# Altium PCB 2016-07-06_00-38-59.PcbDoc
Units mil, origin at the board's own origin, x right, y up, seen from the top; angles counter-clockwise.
Board outline 1500 x 1800 mil, 4 copper layers (Top Layer, MidLayer1, MidLayer2, Bottom Layer); 14 components, 7 nets, 31 pads, 11 vias.
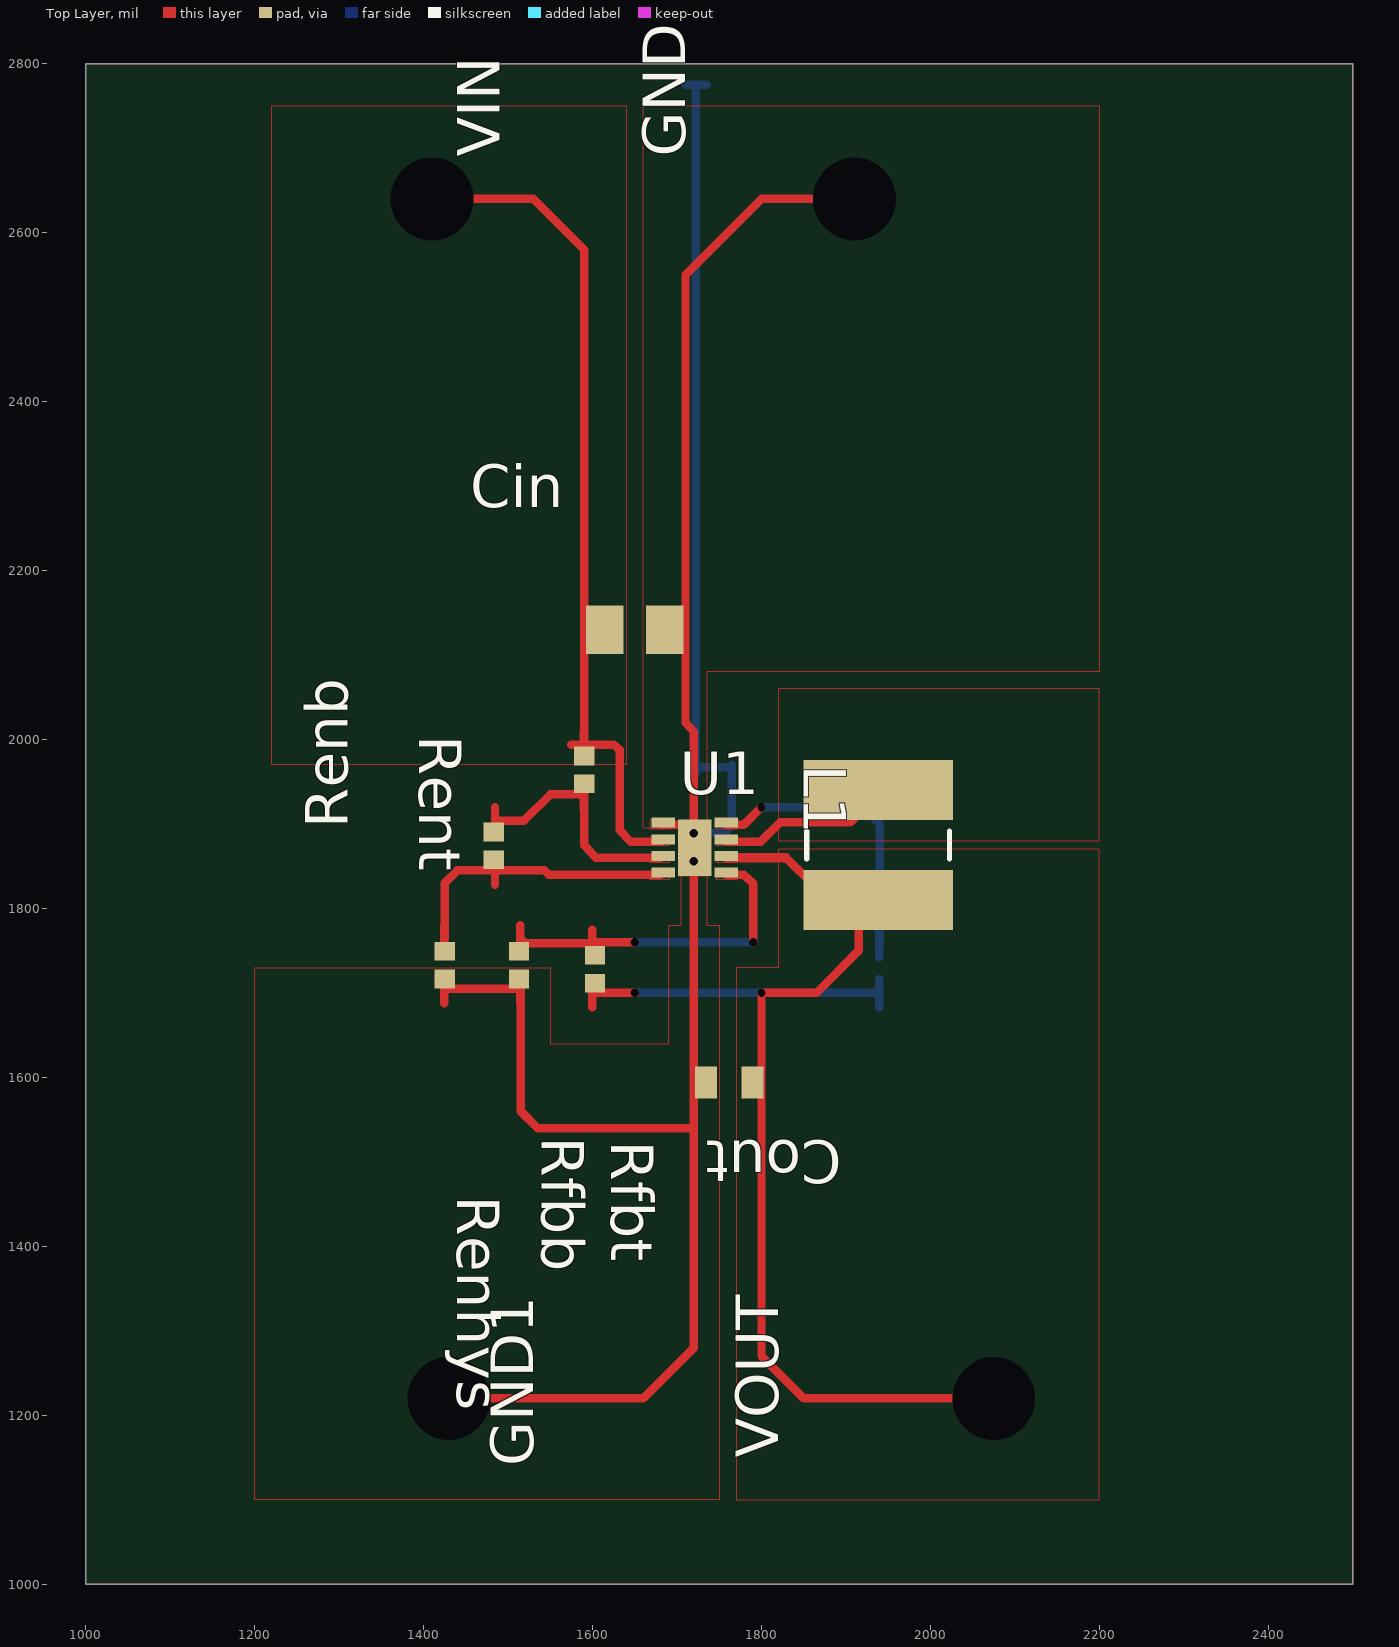
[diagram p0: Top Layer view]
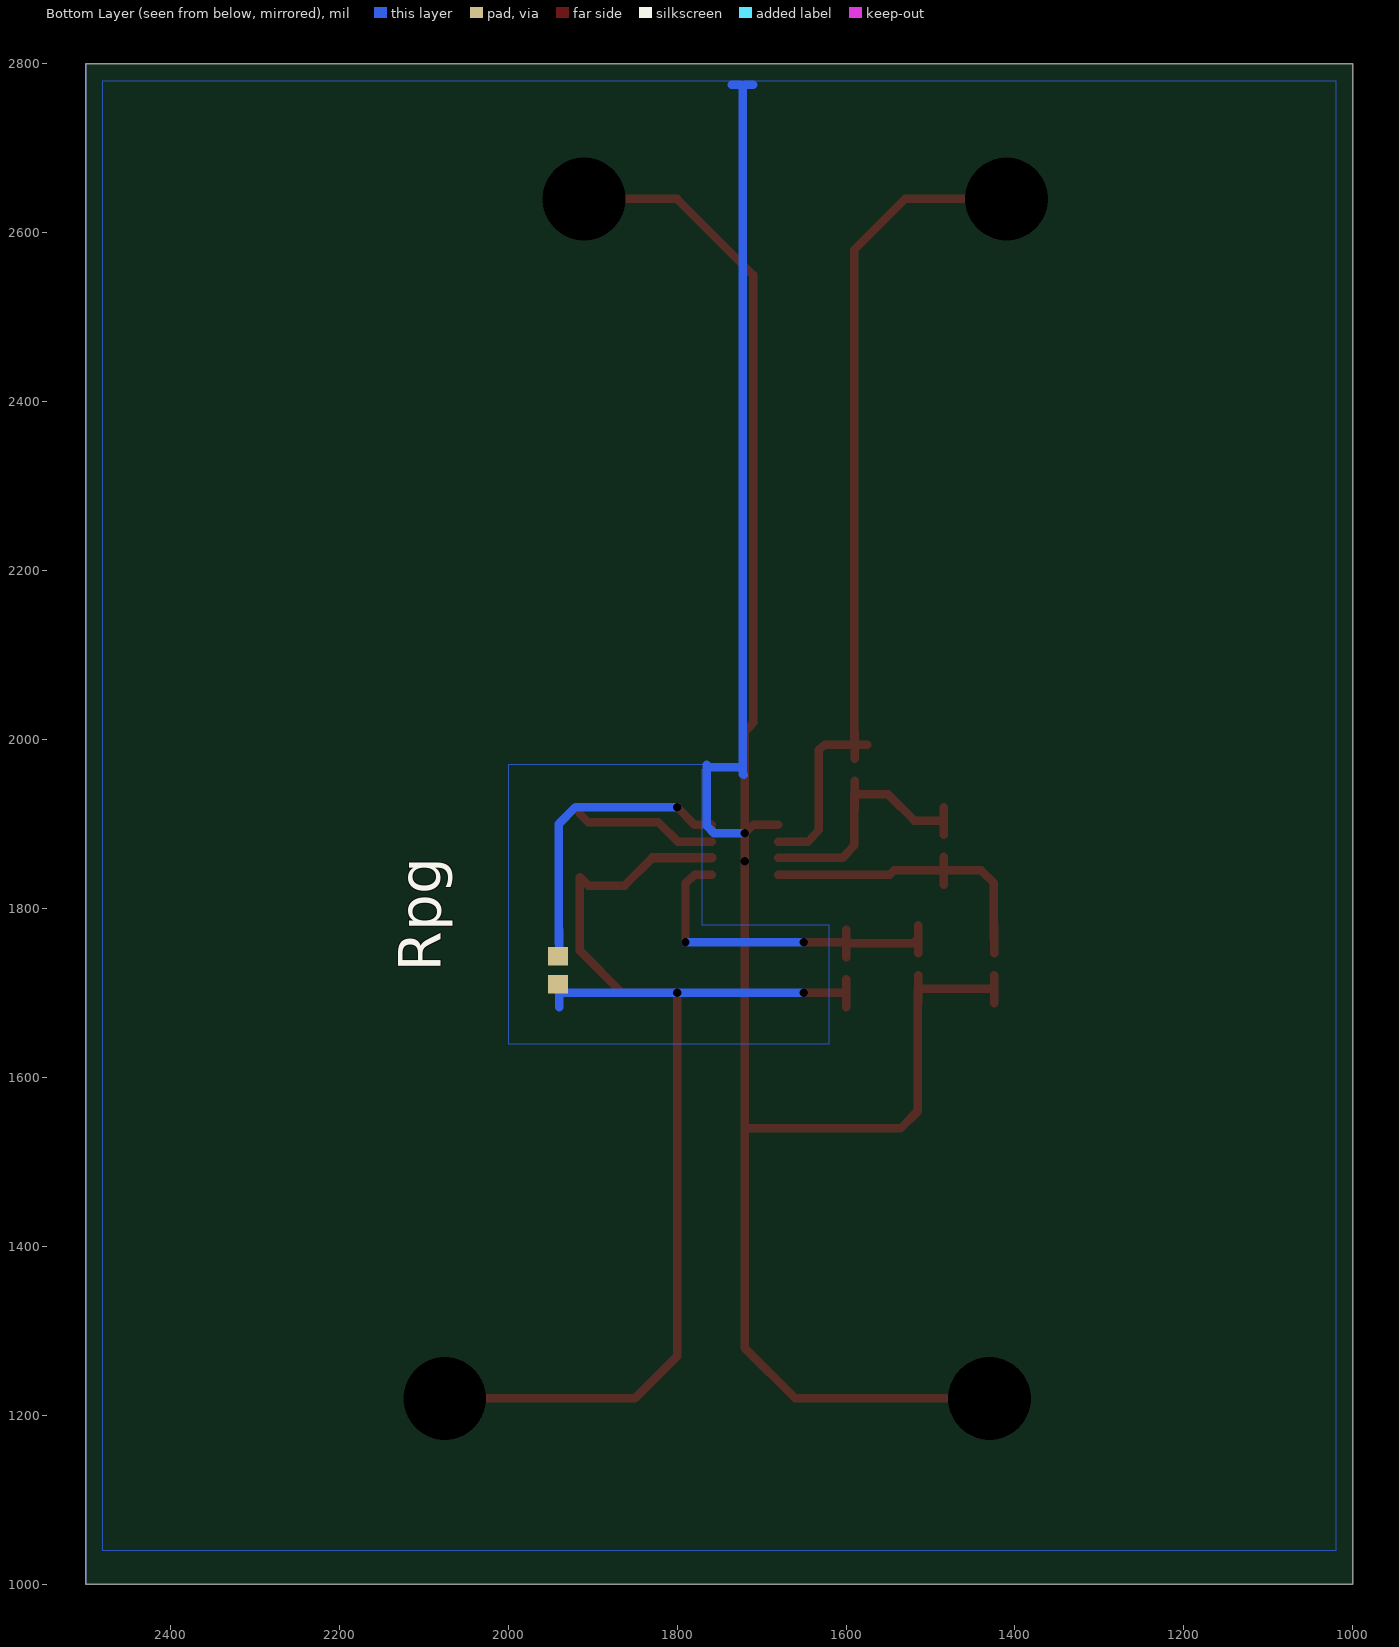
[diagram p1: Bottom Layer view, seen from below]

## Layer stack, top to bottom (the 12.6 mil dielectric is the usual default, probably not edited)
Top Layer: signal copper 1.4
Dielectric: core 12.6, FR-4, Dk 4.8
MidLayer1: signal copper 1.4
Dielectric: prepreg 12.6, FR-4, Dk 4.8
MidLayer2: signal copper 1.4
Dielectric: core 12.6, FR-4, Dk 4.8
Bottom Layer: signal copper 1.4

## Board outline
1000,1000 2500,1000 2500,2800 1000,2800

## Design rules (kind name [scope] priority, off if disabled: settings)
PlaneConnect [All] p0: scope1count=1 scope1_0_kind=Board scope1_0_value=Board scope2count=1 scope2_0_kind=Board scope2_0_value=Board commentlength=0 planeconnectstyle=Direct reliefexpansion=20 reliefentries=4 reliefconductorwidth=10 reliefairgap=10
PlaneConnect [All] p1: planeconnectstyle=Direct reliefexpansion=20 reliefentries=4 reliefconductorwidth=10 reliefairgap=10
PolygonConnect [All] p0: scope1count=1 scope1_0_kind=Board scope1_0_value=Board scope2count=1 scope2_0_kind=Board scope2_0_value=Board commentlength=0 connectstyle=Direct reliefconductorwidth=10 reliefentries=4 polygonreliefangle="90 Angle"
PolygonConnect [All] p1: connectstyle=Direct reliefconductorwidth=10 reliefentries=4 polygonreliefangle="90 Angle"

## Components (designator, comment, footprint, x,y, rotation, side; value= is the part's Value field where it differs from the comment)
Cin "" 0805 1650,2130 r0 top
Cout "" 0603 1762,1594 r180 top
GND "" TP-1502 1909,2638 r90 top
GND1 "" TP-1502 1429,1219 r90 top
L1 "" SDR0403 1938,1875 r270 top
Renb "" 0402#1 1483,1874 r90 top
Renhys "" 0402#1 1425,1733 r270 top
Rent "" 0402#1 1590,1964 r270 top
Rfbb "" 0402#1 1513,1733 r270 top
Rfbt "" 0402#1 1603,1728 r270 top
Rpg "" 0402#2 1941,1727 r270 bottom
U1 "" S-PWSON-N8 1721,1872 r0 top
VIN "" TP-1502 1409,2638 r90 top
VOUT "" TP-1502 2074,1219 r90 top

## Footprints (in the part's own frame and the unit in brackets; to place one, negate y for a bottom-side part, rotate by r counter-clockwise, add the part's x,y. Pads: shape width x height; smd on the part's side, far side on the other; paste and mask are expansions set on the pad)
0402#1 [mil]
  rect 22x24 smd: 1(-16.5,0) 2(16.5,0)
0402#2 [mil]
  rect 22x24 smd: 1(16.5,0) 2(-16.5,0)
0603 [mil]
  rect 26x38 smd: 1(-27.5,0) 2(27.5,0)
0805 [mil]
  rect 44x57 smd: 1(-35.5,0) 2(35.5,0)
S-PWSON-N8 [mm]
  rect 0.705x0.3 smd: 1(-0.952,0.75) 2(-0.952,0.25) 3(-0.952,-0.25) 4(-0.952,-0.75) 5(0.952,-0.75) 6(0.952,-0.25) 7(0.952,0.25) 8(0.952,0.75)
  rect 1x1.7 smd: 9(0,0)
SDR0403 [mil]
  rect 71x177 smd: 1(-65,0) 2(65,0)
  silkscreen extent -16,-84 16,84
TP-1502 [mil]
  round 65 / inner round 0 / far side round 65 hole 32: 1(0,0)

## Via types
v1: diameter 0, hole 10, Top Layer to Bottom Layer, 7 vias
v2: diameter 0, hole 98, Top Layer to Bottom Layer, 4 vias

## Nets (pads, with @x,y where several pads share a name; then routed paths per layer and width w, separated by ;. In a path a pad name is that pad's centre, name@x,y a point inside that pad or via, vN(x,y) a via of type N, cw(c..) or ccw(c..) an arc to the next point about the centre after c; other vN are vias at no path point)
0: Cin.2 Cout.2 GND1.1 GND.1 Renhys.2 Rfbb.2 U1.1 U1.9 | length 3391.8
  Top Layer w10: 1424.5,1688 Renhys.2@1424.5,1721 ; 1425,1705 1515,1705 1515,1560 1535,1540 1720,1540 ; v2(1430,1220) 1660,1220 1720,1280 1720,1540 ; 1514.5,1688 Rfbb.2@1514.5,1721 ; U1.1@1680,1899 1710,1899 v1(1720,1889) ; v2(1910,2640) 1800,2640 1710,2550 1710,2170 1710,2020 1720,2009 v1(1720,1889) ; 1720,1540 1720,1869 v1(1720,1889)
  Bottom Layer w10: 1710,2775 1722,2775 ; v1(1720,1889) 1756,1889 1765,1898 1765,1970 1762,1967 1722,1967 ; 1721,1958 1722,1959 1722,1967 ; 1735,2775 1722,2775 ; 1722,1967 1722,2775
  other v1: 1720,1856
1: Renb.1 Renhys.1 U1.4 | length 395.3
  Top Layer w10: Renhys.1@1424.5,1747 1424.5,1780 ; 1425,1764 1425,1830 1440,1845 1485,1845 1543,1845 1548,1840 U1.4@1680,1840 ; 1484.5,1828 Renb.1@1484.5,1861
2: Renb.2 Rent.2 U1.3 | length 340.4
  Top Layer w10: Renb.2@1484.5,1887 1484.5,1920 ; 1485,1904 1519,1904 1550,1935 1590,1935 1590,1875 1604,1860 U1.3@1680,1860 ; 1589.5,1918 Rent.2@1589.5,1951
5: Rfbb.1 Rfbt.1 U1.5 | length 448.9
  Top Layer w10: Rfbb.1@1514.5,1747 1514.5,1780 ; 1515,1764 1520,1759 1600,1759 1600,1760 v1(1650,1760) ; Rfbt.1@1599.5,1742 1599.5,1775 ; U1.5@1759,1840 1779,1840 1790,1830 v1(1790,1760)
  Bottom Layer w10: v1(1650,1760) v1(1790,1760)
6: Cout.1 L1.1 L1.2 Rfbt.2 Rpg.1 U1.6 U1.7 VOUT.1 | length 1697.9
  Top Layer w10: 1599.5,1683 Rfbt.2@1599.5,1716 ; 1600,1700 v1(1650,1700) ; U1.7@1759,1879 1799,1879 1822,1902 1905,1902 L1.1@1915,1912 ; 1829,1860 1862,1827 1905,1827 1915,1837 1915,1750 1865,1700 v1(1800,1700) 1800,1540 1800,1270 1850,1220 v2(2075,1220)
  Top Layer w11: U1.6@1759,1860 1829,1860
  Bottom Layer w10: v1(1650,1700) v1(1800,1700) 1939,1700 Rpg.1@1940,1700 ; 1939.5,1683 Rpg.1@1939.5,1716
8: Cin.1 Rent.1 U1.2 VIN.1 | length 1032.2
  Top Layer w10: v2(1410,2640) 1530,2640 1590,2580 1590,2170 1590,1994 ; 1575,1994 1590,1994 ; Rent.1@1589.5,1977 1589.5,2010 ; U1.2@1680,1879 1645,1879 1632,1893 1632,1988 1625,1994 1590,1994
12: Rpg.2 U1.8 | length 372
  Top Layer w10: U1.8@1759,1899 1779,1899 v1(1800,1920)
  Bottom Layer w10: v1(1800,1920) 1920,1920 1940,1900 1940,1759 ; Rpg.2@1939.5,1742 1939.5,1775

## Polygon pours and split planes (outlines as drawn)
12 on Top Layer " " (solid, pour order 0): 1747,1894 1747,1905 1770,1905 1770,1894
6 on Top Layer " " (solid, pour order 1): 1747,1874 1747,1885 1770,1885 1770,1874
6 on Top Layer " " (solid, pour order 2): 1747,1854 1747,1865 1770,1865 1770,1854
5 on Top Layer " " (solid, pour order 3): 1747,1834 1747,1845 1770,1845 1770,1834
1 on Top Layer " " (solid, pour order 4): 1668,1834 1668,1845 1691,1845 1691,1834
2 on Top Layer " " (solid, pour order 5): 1668,1854 1668,1865 1691,1865 1691,1854
8 on Top Layer " " (solid, pour order 6): 1668,1874 1668,1885 1691,1885 1691,1874
6 on Top Layer " " (solid, pour order 7): 1820,1880 2200,1880 2200,2060 1820,2060
8 on Top Layer " " (solid, pour order 8): 1640,2750 1640,1970 1220,1970 1220,2750
6 on Top Layer " " (solid, pour order 9): 1820,1870 1820,1730 1770,1730 1770,1100 2200,1100 2200,1870
0 on Top Layer " " (solid, pour order 10): 1702,1838 1702,1900 1737,1900 1737,1838
0 on Top Layer " " (solid, pour order 11): 1668,1894 1668,1905 1691,1905 1691,1894
0 on Top Layer " " (solid, pour order 12): 1705,1895 1660,1895 1660,2750 2200,2750 2200,2080 1735,2080 1735,1780 1750,1780 1750,1100 1200,1100 1200,1730 1550,1730 1550,1640 1690,1640 1690,1780 1705,1780
0 on Bottom Layer " " (solid, pour order 13): 1020,1040 2480,1040 2480,2780 1725,2780 1725,1970 2000,1970 2000,1640 1620,1640 1620,1780 1770,1780 1770,1965 1720,1965 1720,2780 1020,2780

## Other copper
Multi-Layer:
  the board outline again, w1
